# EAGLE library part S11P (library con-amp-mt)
AMP MT CONNECTOR
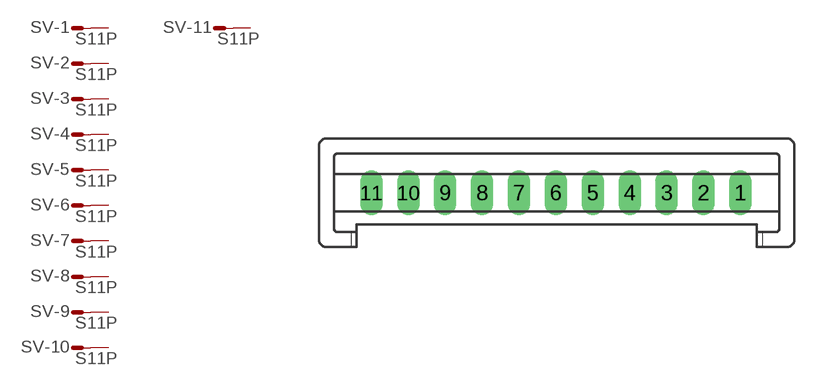
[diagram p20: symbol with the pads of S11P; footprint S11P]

Designator prefix SV; gates -1=M -2=M -3=M -4=M -5=M -6=M -7=M -8=M -9=M -10=M -11=M

## S11P (OC_FARNELL: unknown; OC_NEWARK: unknown)  [S11P]
1  -1:S  pas
2  -2:S  pas
3  -3:S  pas
4  -4:S  pas
5  -5:S  pas
6  -6:S  pas
7  -7:S  pas
8  -8:S  pas
9  -9:S  pas
10  -10:S  pas
11  -11:S  pas

## Footprint S11P (pad centres in mm)
AMP MT CONNECTOR
drill 1.016 long: 1 12.5,0; 2 10,0; 3 7.5,0; 4 5,0; 5 2.5,0; 6 0,0; 7 -2.5,0; 8 -5,0; 9 -7.5,0; 10 -10,0; 11 -12.5,0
